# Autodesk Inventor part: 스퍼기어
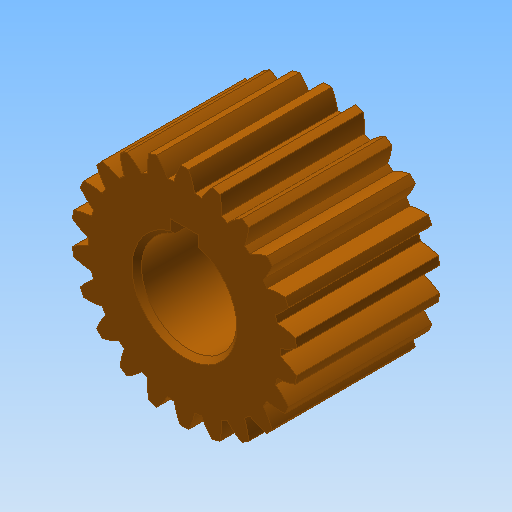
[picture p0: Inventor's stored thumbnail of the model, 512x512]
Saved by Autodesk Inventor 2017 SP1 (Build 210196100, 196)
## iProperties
Created: 2019-03
Part Number: 스퍼기어
Material: 강철
Document SubType Name: Modeling
Designer: mduedu
Categories: <?xml version="1.0" encoding="UTF-16"?> <MemberInstance><Categories><FamilyTemplate><FamilyTemplateParameter ValueType="xs:double" Id="1" ObjectReferenceKey="da
Density: 1 g/cm^3
Appearance: 주황색
CustomPartVersion: 1
Author: mduedu
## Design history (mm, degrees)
sketch "Sketch1"
  geometry: C1 r 23.6 at (0, 0)
  constraints: 1 centre point
  dimensions: "d0" = 47.2 diameter of C1 (= da_da)
extrude "Extrusion1" new body sketch "Sketch1" distance "d1" = 30 (= da_b); taper "d2" = 0 deg
workplane "Work Plane2"
sketch "Sketch2"
  geometry: C1 r 23.6 at (0, 0) reference; C2 r 22 at (0, 0)
  constraints: 1 centre point, 1 coincident
  dimensions: "d3" = 44 diameter of C2 (= da_dw)
feature "피치 지름" sketch "Sketch2" dims "d4" = 10, "d5" = 0
workplane "Work Plane8"
workplane "Work Plane9"
feature "스퍼 기어" dims "da_b" = 30, "da_d" = 44, "da_aw" = 44, "da_da" = 47.2, "da_df" = 40.172, "da_dw" = 44, angle "da_beta" = 0 deg, "da_lefttooth" = 0, "da_righttooth" = 0
sketch "스케치3"
  geometry: L1 (-3, 9.539)-(3, 9.539); L2 (3, 9.539)-(3, 12.8); L3 (3, 12.8)-(-3, 12.8); L4 (-3, 12.8)-(-3, 9.539); A1 r 10 centre (0, 0) between (-3, 9.539) and (3, 9.539); 1 further point
  constraints: 8 end point, 2 parallel, 2 point on circle, 1 centre point, 1 coincident, 1 horizontal, 1 perpendicular
  dimensions: "d49" = 20 diameter of A1; "d50" = 6 distance of L2.end L3.end; "d51" = 22.8 dimension on A1 L3
extrude "돌출2" cut sketch "스케치3" stored distance "d52" = 10; taper "d53" = 0 deg
chamfer "모따기1" distance "d54" = 1; stored, may be unused: second distance "d55" = 2, angle "d56" = 45 deg
body "Solid1"
body "Srf1"
other parameters: "d16" = 44 (= da_aw), "d17" = 0, "d34" = 1.428 (computed from da_z), "d39" = 0, "d41" = 0, "d43" = 44 (= da_aw), "d46" = 44 (= da_aw), "d47" = 0, "d48" = 0
